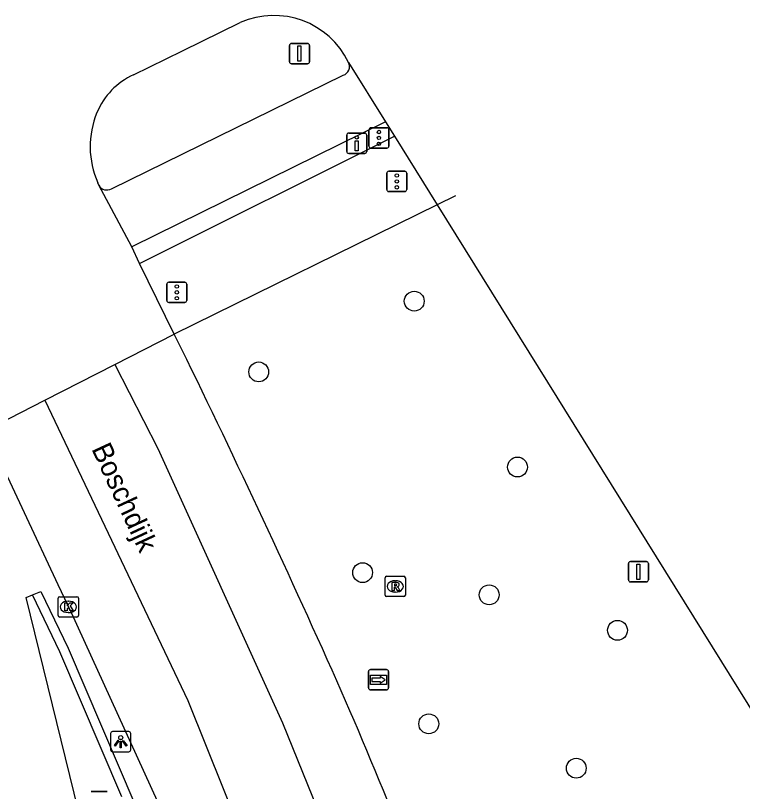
# Model space of a CAD drawing. Extents: x 160304 to 160954, y 383686 to 384161.
# Drawn here: x 160880.02 to 160915.89, y 383894.46 to 383932.75 of the extents above; entities that cross this region are included whole.
import ezdxf

# ---------------------------------------------------------------- set-up
doc = ezdxf.new("R2010")
doc.units = 0
for name, color, linetype in [('IMGEO_Boom', 7, 'Continuous'), ('IMGEO_Drukknoppaal', 7, 'Continuous'), ('IMGEO_Fietspad_open', 7, 'Continuous'), ('IMGEO_Kolk', 7, 'Continuous'), ('IMGEO_Lichtpunt', 7, 'Continuous'), ('IMGEO_Muur', 7, 'Continuous'), ('IMGEO_Openbare_ruimte_label', 7, 'Continuous'), ('IMGEO_Portaal', 7, 'Continuous'), ('IMGEO_Rijbaan_lokaal_gesloten', 7, 'Continuous'), ('IMGEO_Rioolput', 7, 'Continuous'), ('IMGEO_Verkeersbordpaal', 7, 'Continuous'), ('IMGEO_Verkeersregelinstallatiepaal', 7, 'Continuous'), ('IMGEO_Voetpad_open', 7, 'Continuous'), ('IMGEO_Wegwijzer', 7, 'Continuous')]:
    doc.layers.add(name, color=color, linetype=linetype)

msp = doc.modelspace()

# ---------------------------------------------------------------- linework, layer by layer
at = {"layer": 'IMGEO_Boom'}
for centre in [(160899.695, 383918.654), (160892.024, 383915.164), (160904.791, 383910.47), (160897.148, 383905.256), (160903.393, 383904.162), (160909.723, 383902.409), (160900.414, 383897.794), (160907.691, 383895.604)]:
    msp.add_circle(centre, 0.489, dxfattribs=at)
at = {"layer": 'IMGEO_Drukknoppaal'}
for p, q in [((160896.364, 383926.047), (160896.364, 383926.847)), ((160896.364, 383926.847), (160896.364, 383926.047)), ((160896.464, 383926.947), (160897.254, 383926.947)), ((160897.254, 383926.947), (160896.464, 383926.947)), ((160897.354, 383926.847), (160897.354, 383926.047)), ((160897.354, 383926.047), (160897.354, 383926.847)), ((160897.254, 383925.947), (160896.464, 383925.947)), ((160896.464, 383925.947), (160897.254, 383925.947))]:
    msp.add_line(p, q, dxfattribs=at)
msp.add_lwpolyline([(160896.934, 383926.572), (160896.934, 383926.072), (160896.784, 383926.072), (160896.784, 383926.572), (160896.934, 383926.572)], dxfattribs=at)
msp.add_circle((160896.859, 383926.737), 0.085, dxfattribs=at)
for centre, start, end in [((160896.464, 383926.847), 90, 180), ((160896.464, 383926.847), 90, 180), ((160897.254, 383926.847), 0, 90), ((160897.254, 383926.847), 360, 90), ((160896.464, 383926.047), 180, 270), ((160896.464, 383926.047), 180, 270), ((160897.254, 383926.047), 270, 0), ((160897.254, 383926.047), 270, 0)]:
    msp.add_arc(centre, 0.1, start, end, dxfattribs=at)
at = {"layer": 'IMGEO_Fietspad_open'}
for points in [[(160884.755, 383924.199), (160896.193, 383929.804)], [(160898.282, 383927.509), (160885.755, 383921.333)]]:
    msp.add_lwpolyline(points, dxfattribs=at)
for centre, radius, start, end in [((160896.056, 383930.235), 0.452, 287.6991, 27.1251), ((160884.532, 383924.599), 0.458, 209.5707, 299.1243)]:
    msp.add_arc(centre, radius, start, end, dxfattribs=at)
at = {"layer": 'IMGEO_Kolk'}
for p, q in [((160882.13, 383903.141), (160882.13, 383903.993)), ((160882.205, 383904.067), (160883.057, 383904.067)), ((160882.618, 383903.847), (160882.643, 383903.847)), ((160883.131, 383903.993), (160883.131, 383903.141)), ((160883.057, 383903.067), (160882.205, 383903.067)), ((160882.641, 383903.287), (160882.616, 383903.287))]:
    msp.add_line(p, q, dxfattribs=at)
for points in [[(160882.13, 383903.141), (160882.13, 383903.993)], [(160882.205, 383904.067), (160883.057, 383904.067)], [(160883.131, 383903.993), (160883.131, 383903.141)], [(160882.451, 383903.767), (160882.574, 383903.767), (160882.574, 383903.616), (160882.704, 383903.767), (160882.868, 383903.767), (160882.722, 383903.616), (160882.875, 383903.367), (160882.723, 383903.367), (160882.638, 383903.531), (160882.574, 383903.464), (160882.574, 383903.367), (160882.451, 383903.367), (160882.451, 383903.767)], [(160883.057, 383903.067), (160882.205, 383903.067)]]:
    msp.add_lwpolyline(points, dxfattribs=at)
for centre, start, end in [((160882.207, 383903.991), 91.552, 178.448), ((160882.207, 383903.991), 91.552, 178.448), ((160883.055, 383903.991), 1.552, 88.448), ((160883.055, 383903.991), 1.552, 88.448), ((160882.207, 383903.143), 181.552, 268.448), ((160882.207, 383903.143), 181.552, 268.448), ((160883.055, 383903.143), 271.552, 358.448), ((160883.055, 383903.143), 271.552, 358.448)]:
    msp.add_arc(centre, 0.0765, start, end, dxfattribs=at)
for centre, major_axis, ratio, start_param, end_param in [((160882.617, 383903.567), (-0.387, 0.002), 0.722429, 4.712389, 7.853982), ((160882.642, 383903.567), (-0.39, 0.002), 0.717154, 1.570796, 4.712389)]:
    msp.add_ellipse(centre, major_axis=major_axis, ratio=ratio, start_param=start_param, end_param=end_param, dxfattribs=at)
at = {"layer": 'IMGEO_Lichtpunt'}
for p, q in [((160884.716, 383897.316), (160884.716, 383896.509)), ((160884.716, 383897.316), (160884.716, 383896.509)), ((160885.618, 383897.411), (160884.81, 383897.411)), ((160885.618, 383897.411), (160884.81, 383897.411)), ((160885.712, 383896.509), (160885.712, 383897.316)), ((160885.712, 383896.509), (160885.712, 383897.316)), ((160884.81, 383896.415), (160885.618, 383896.415)), ((160884.81, 383896.415), (160885.618, 383896.415))]:
    msp.add_line(p, q, dxfattribs=at)
for points in [[(160885.09, 383896.98), (160885.129, 383896.952), (160884.941, 383896.69), (160884.903, 383896.717), (160885.09, 383896.98)], [(160885.192, 383896.932), (160885.239, 383896.932), (160885.239, 383896.61), (160885.192, 383896.61), (160885.192, 383896.932)], [(160885.302, 383896.952), (160885.34, 383896.979), (160885.527, 383896.717), (160885.488, 383896.689), (160885.302, 383896.952)]]:
    msp.add_lwpolyline(points, dxfattribs=at)
msp.add_circle((160885.215, 383897.114), 0.0994, dxfattribs=at)
for centre, start, end in [((160884.81, 383897.316), 90, 180), ((160884.81, 383897.316), 90, 180), ((160885.618, 383897.316), 0, 90), ((160885.618, 383897.316), 0, 90), ((160884.81, 383896.509), 180, 270), ((160884.81, 383896.509), 180, 270), ((160885.618, 383896.509), 270, 0), ((160885.618, 383896.509), 270, 360)]:
    msp.add_arc(centre, 0.0946, start, end, dxfattribs=at)
at = {"layer": 'IMGEO_Muur'}
for points in [[(160880.862, 383904.157), (160881.279, 383904.328), (160882.628, 383901.534), (160888.383, 383888.052), (160894.472, 383871.868), (160908.403, 383833.697), (160908.635, 383832.485), (160908.704, 383829.792), (160908.379, 383827.413), (160908.031, 383826.069), (160907.563, 383824.758), (160906.981, 383823.495), (160906.288, 383822.289), (160905.49, 383821.15), (160904.593, 383820.086), (160903.605, 383819.107), (160902.533, 383818.22)], [(160885.276, 383894.185), (160882.218, 383901.348), (160880.862, 383904.157)]]:
    msp.add_lwpolyline(points, dxfattribs=at)
at = {"layer": 'IMGEO_Portaal'}
for p, q in [((160893.539, 383930.474), (160893.539, 383931.274)), ((160893.539, 383931.274), (160893.539, 383930.474)), ((160893.639, 383931.374), (160894.429, 383931.374)), ((160894.429, 383931.374), (160893.639, 383931.374)), ((160894.529, 383931.274), (160894.529, 383930.474)), ((160894.529, 383930.474), (160894.529, 383931.274)), ((160894.429, 383930.374), (160893.639, 383930.374)), ((160893.639, 383930.374), (160894.429, 383930.374))]:
    msp.add_line(p, q, dxfattribs=at)
msp.add_lwpolyline([(160893.959, 383931.249), (160894.109, 383931.249), (160894.109, 383930.499), (160893.959, 383930.499), (160893.959, 383931.249)], dxfattribs=at)
for centre, start, end in [((160893.639, 383931.274), 90, 180), ((160893.639, 383931.274), 90, 180), ((160894.429, 383931.274), 0, 90), ((160894.429, 383931.274), 360, 90), ((160893.639, 383930.474), 180, 270), ((160893.639, 383930.474), 180, 270), ((160894.429, 383930.474), 270, 0), ((160894.429, 383930.474), 270, 0)]:
    msp.add_arc(centre, 0.1, start, end, dxfattribs=at)
at = {"layer": 'IMGEO_Rijbaan_lokaal_gesloten'}
for points in [[(160885.839, 383929.825), (160888.257, 383931.007), (160891.115, 383932.404)], [(160896.458, 383930.441), (160898.282, 383927.509)], [(160898.282, 383927.509), (160898.728, 383926.791)], [(160898.728, 383926.791), (160900.833, 383923.408)], [(160884.134, 383924.373), (160884.086, 383924.501)], [(160885.755, 383921.333), (160884.134, 383924.373)], [(160901.725, 383923.859), (160900.833, 383923.408)], [(160900.833, 383923.408), (160917.077, 383897.29), (160945.108, 383852.141), (160948.035, 383847.457), (160949.052, 383845.722), (160950.531, 383843.067)], [(160886.14, 383920.521), (160885.755, 383921.333)], [(160887.859, 383917.022), (160886.14, 383920.521)], [(160884.917, 383915.524), (160887.859, 383917.022)], [(160887.955, 383916.832), (160887.859, 383917.022)], [(160881.476, 383913.772), (160884.917, 383915.524)], [(160884.917, 383915.524), (160887.049, 383911.378), (160893.201, 383897.836), (160897.631, 383886.88), (160907.713, 383858.522), (160920.564, 383822.935)], [(160878.538, 383912.275), (160881.476, 383913.772)], [(160881.476, 383913.772), (160888.531, 383898.942), (160896.529, 383878.998), (160914.965, 383826.437)], [(160878.77, 383911.782), (160882.114, 383904.67), (160882.763, 383903.289), (160887.021, 383894.001), (160894.332, 383875.048), (160899.607, 383860.926), (160906.136, 383843.553), (160908.651, 383836.68), (160909.019, 383835.673), (160909.351, 383834.464), (160909.573, 383833.23), (160909.685, 383831.98), (160909.684, 383830.726), (160909.717, 383830.432), (160909.764, 383829.565), (160909.732, 383828.698), (160909.624, 383827.836), (160909.438, 383826.988), (160909.178, 383826.16), (160908.877, 383825.212), (160908.34, 383823.878), (160908.325, 383823.849)]]:
    msp.add_lwpolyline(points, dxfattribs=at)
for centre, radius, start, end in [((160892.77, 383928.656), 4.097, 25.8228, 113.8309), ((160887.301, 383926.617), 3.525, 114.4969, 157.5397), ((160888.067, 383926.282), 4.361, 157.3162, 204.1066), ((160414.384, 383684.701), 527.404, 24.08259, 26.11272), ((160677.37, 383804.12), 238.585, 19.56984, 23.6716)]:
    msp.add_arc(centre, radius, start, end, dxfattribs=at)
at = {"layer": 'IMGEO_Rioolput'}
for p, q in [((160898.257, 383904.149), (160898.257, 383905.001)), ((160898.332, 383905.075), (160899.184, 383905.075)), ((160899.258, 383905.001), (160899.258, 383904.149)), ((160898.745, 383904.855), (160898.77, 383904.855)), ((160898.768, 383904.295), (160898.743, 383904.295)), ((160899.184, 383904.075), (160898.332, 383904.075))]:
    msp.add_line(p, q, dxfattribs=at)
for points in [[(160898.257, 383904.149), (160898.257, 383905.001)], [(160898.332, 383905.075), (160899.184, 383905.075)], [(160899.258, 383905.001), (160899.258, 383904.149)], [(160898.846, 383904.773), (160898.594, 383904.775), (160898.594, 383904.375)], [(160898.772, 383904.694), (160898.718, 383904.694), (160898.718, 383904.613)], [(160898.718, 383904.613), (160898.77, 383904.613)], [(160898.594, 383904.375), (160898.718, 383904.375), (160898.718, 383904.537), (160898.729, 383904.537)], [(160898.776, 383904.508), (160898.847, 383904.375), (160898.987, 383904.375), (160898.922, 383904.501)], [(160899.184, 383904.075), (160898.332, 383904.075)]]:
    msp.add_lwpolyline(points, dxfattribs=at)
for centre, radius, start, end in [((160898.334, 383904.999), 0.0765, 91.552, 178.448), ((160898.334, 383904.999), 0.0765, 91.552, 178.448), ((160899.182, 383904.999), 0.0765, 1.552, 88.448), ((160899.182, 383904.999), 0.0765, 1.552, 88.448), ((160898.754, 383904.802), 0.19, 274.7715, 282.9687), ((160898.778, 383904.598), 0.0964, 77.0061, 93.1865), ((160898.792, 383904.655), 0.0378, 276.6634, 79.6772), ((160898.845, 383904.663), 0.109, 350.3612, 89.416), ((160898.843, 383904.663), 0.112, 277.5842, 350.9817), ((160898.728, 383904.484), 0.0533, 26.0293, 88.6989), ((160898.827, 383904.448), 0.108, 29.5134, 73.7905), ((160898.334, 383904.151), 0.0765, 181.552, 268.448), ((160898.334, 383904.151), 0.0765, 181.552, 268.448), ((160899.182, 383904.151), 0.0765, 271.552, 358.448), ((160899.182, 383904.151), 0.0765, 271.552, 358.448)]:
    msp.add_arc(centre, radius, start, end, dxfattribs=at)
for centre, major_axis, ratio, start_param, end_param in [((160898.744, 383904.575), (-0.387, 0.002), 0.722429, 4.712389, 7.853982), ((160898.769, 383904.575), (-0.39, 0.002), 0.717154, 1.570796, 4.712389)]:
    msp.add_ellipse(centre, major_axis=major_axis, ratio=ratio, start_param=start_param, end_param=end_param, dxfattribs=at)
at = {"layer": 'IMGEO_Verkeersbordpaal'}
for p, q in [((160910.363, 383905.8), (160911.153, 383905.8)), ((160911.153, 383905.8), (160910.363, 383905.8)), ((160910.263, 383904.9), (160910.263, 383905.7)), ((160910.263, 383905.7), (160910.263, 383904.9)), ((160911.253, 383905.7), (160911.253, 383904.9)), ((160911.253, 383904.9), (160911.253, 383905.7)), ((160911.153, 383904.8), (160910.363, 383904.8)), ((160910.363, 383904.8), (160911.153, 383904.8))]:
    msp.add_line(p, q, dxfattribs=at)
msp.add_lwpolyline([(160910.683, 383905.675), (160910.833, 383905.675), (160910.833, 383904.925), (160910.683, 383904.925), (160910.683, 383905.675)], dxfattribs=at)
for centre, start, end in [((160910.363, 383905.7), 90, 180), ((160910.363, 383905.7), 90, 180), ((160911.153, 383905.7), 0, 90), ((160911.153, 383905.7), 360, 90), ((160910.363, 383904.9), 180, 270), ((160910.363, 383904.9), 180, 270), ((160911.153, 383904.9), 270, 0), ((160911.153, 383904.9), 270, 0)]:
    msp.add_arc(centre, 0.1, start, end, dxfattribs=at)
at = {"layer": 'IMGEO_Verkeersregelinstallatiepaal'}
for p, q in [((160897.557, 383927.212), (160898.347, 383927.212)), ((160898.347, 383927.212), (160897.557, 383927.212)), ((160897.457, 383926.312), (160897.457, 383927.112)), ((160897.457, 383927.112), (160897.457, 383926.312)), ((160898.447, 383927.112), (160898.447, 383926.312)), ((160898.447, 383926.312), (160898.447, 383927.112)), ((160898.347, 383926.212), (160897.557, 383926.212)), ((160897.557, 383926.212), (160898.347, 383926.212)), ((160898.34, 383924.165), (160898.34, 383924.965)), ((160898.34, 383924.965), (160898.34, 383924.165)), ((160898.44, 383925.065), (160899.23, 383925.065)), ((160899.23, 383925.065), (160898.44, 383925.065)), ((160899.33, 383924.965), (160899.33, 383924.165)), ((160899.33, 383924.165), (160899.33, 383924.965)), ((160899.23, 383924.065), (160898.44, 383924.065)), ((160898.44, 383924.065), (160899.23, 383924.065)), ((160887.586, 383919.59), (160888.376, 383919.59)), ((160888.376, 383919.59), (160887.586, 383919.59)), ((160887.486, 383918.69), (160887.486, 383919.49)), ((160887.486, 383919.49), (160887.486, 383918.69)), ((160888.476, 383919.49), (160888.476, 383918.69)), ((160888.476, 383918.69), (160888.476, 383919.49)), ((160888.376, 383918.59), (160887.586, 383918.59)), ((160887.586, 383918.59), (160888.376, 383918.59))]:
    msp.add_line(p, q, dxfattribs=at)
for centre in [(160897.952, 383927.002), (160897.952, 383926.712), (160897.952, 383926.422), (160898.835, 383924.855), (160898.835, 383924.565), (160898.835, 383924.275), (160887.981, 383919.38), (160887.981, 383919.09), (160887.981, 383918.8)]:
    msp.add_circle(centre, 0.085, dxfattribs=at)
for centre, start, end in [((160897.557, 383927.112), 90, 180), ((160897.557, 383927.112), 90, 180), ((160898.347, 383927.112), 0, 90), ((160898.347, 383927.112), 360, 90), ((160897.557, 383926.312), 180, 270), ((160897.557, 383926.312), 180, 270), ((160898.347, 383926.312), 270, 0), ((160898.347, 383926.312), 270, 0), ((160898.44, 383924.965), 90, 180), ((160898.44, 383924.965), 90, 180), ((160899.23, 383924.965), 0, 90), ((160899.23, 383924.965), 360, 90), ((160898.44, 383924.165), 180, 270), ((160898.44, 383924.165), 180, 270), ((160899.23, 383924.165), 270, 0), ((160899.23, 383924.165), 270, 0), ((160887.586, 383919.49), 90, 180), ((160887.586, 383919.49), 90, 180), ((160888.376, 383919.49), 0, 90), ((160888.376, 383919.49), 360, 90), ((160887.586, 383918.69), 180, 270), ((160887.586, 383918.69), 180, 270), ((160888.376, 383918.69), 270, 0), ((160888.376, 383918.69), 270, 0)]:
    msp.add_arc(centre, 0.1, start, end, dxfattribs=at)
at = {"layer": 'IMGEO_Voetpad_open'}
for points in [[(160886.14, 383920.521), (160898.728, 383926.791)], [(160900.833, 383923.408), (160887.859, 383917.022)], [(160902.267, 383818.561), (160900.17, 383824.023), (160880.544, 383904.027), (160880.862, 383904.157)]]:
    msp.add_lwpolyline(points, dxfattribs=at)
at = {"layer": 'IMGEO_Wegwijzer'}
for p, q in [((160897.438, 383899.57), (160897.438, 383900.37)), ((160897.438, 383900.37), (160897.438, 383899.57)), ((160897.538, 383900.47), (160898.328, 383900.47)), ((160898.328, 383900.47), (160897.538, 383900.47)), ((160898.428, 383900.37), (160898.428, 383899.57)), ((160898.428, 383899.57), (160898.428, 383900.37)), ((160898.328, 383899.47), (160897.538, 383899.47)), ((160897.538, 383899.47), (160898.328, 383899.47)), ((160883.761, 383894.456), (160884.551, 383894.456)), ((160884.551, 383894.456), (160883.761, 383894.456))]:
    msp.add_line(p, q, dxfattribs=at)
for points in [[(160897.539, 383900.202), (160898.327, 383900.202), (160898.327, 383899.738), (160897.539, 383899.738), (160897.539, 383900.202)], [(160897.604, 383900.054), (160897.604, 383899.97), (160897.604, 383899.886), (160898.015, 383899.886), (160898.015, 383899.803), (160898.262, 383899.97), (160898.015, 383900.137), (160898.015, 383900.054), (160897.604, 383900.054)]]:
    msp.add_lwpolyline(points, dxfattribs=at)
for centre, start, end in [((160897.538, 383900.37), 90, 180), ((160897.538, 383900.37), 90, 180), ((160898.328, 383900.37), 0, 90), ((160898.328, 383900.37), 360, 90), ((160897.538, 383899.57), 180, 270), ((160897.538, 383899.57), 180, 270), ((160898.328, 383899.57), 270, 0), ((160898.328, 383899.57), 270, 0)]:
    msp.add_arc(centre, 0.1, start, end, dxfattribs=at)

# ---------------------------------------------------------------- texts
at = {"layer": 'IMGEO_Openbare_ruimte_label'}
msp.add_text('Boschdijk', height=1, rotation=294.8992, dxfattribs=at).set_placement((160883.755, 383911.367))

doc.saveas('drawing.dxf')
